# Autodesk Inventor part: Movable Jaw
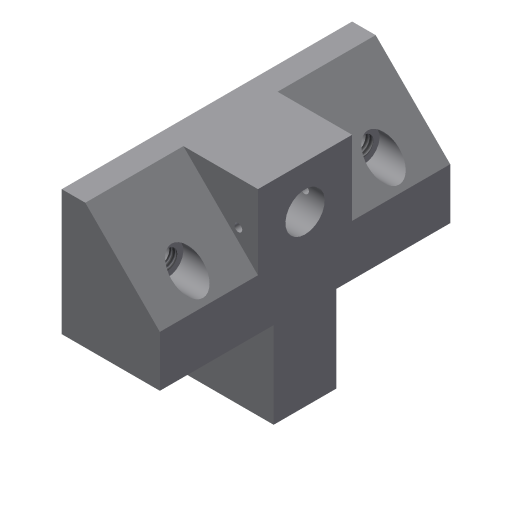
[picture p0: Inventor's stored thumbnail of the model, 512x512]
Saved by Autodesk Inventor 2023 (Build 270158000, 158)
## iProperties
Shininess: 77.0
Length Units: 11269
Angle Units: 11279
Time Units: 11290
Mass Units: 11283
Length Display Precision: 3
Angle Display Precision: 2
Created: 2002-02
Part Number: Movable Jaw
Document SubType Name: Modeling
Designer: ***
Density: 1 g/cm^3
Material: Generic
Mass: 56.5588 g
Surface Area: 124.299 cm^2
Volume: 56.5588 cm^3
Appearance: Default
Density: 0.0
Volumn: 0.0
Area: 0.0
PropertySet Name: Model Information
Control State: 0
Master: False
Checked Out: False
Author: ***
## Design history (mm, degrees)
sketch "Sketch2"
  geometry: L1 (2.39, 41.509)-(2.39, 9.509); L2 (2.39, 9.509)-(-22.61, 9.509); L3 (-22.61, 9.509)-(-22.61, 22.509); L4 (-22.61, 22.509)-(-3.61, 41.509); L5 (-3.61, 41.509)-(2.39, 41.509)
  constraints: 10 end point, 2 parallel, 1 perpendicular, 1 vertical
  dimensions: "d0" = 25 distance of L1.end L2.end; "d2" = 13 distance of L2.end L3.end; "d3" = 32 distance between parallel lines of L5 L2; "d4" = 6 distance of L4.end L1.start
extrude "Extrusion1" new body sketch "Sketch2" stored distance "d5" = 74; taper "d6" = 0 deg
sketch "Sketch3"
  geometry: L1 (-19, 25)-(11, 25); L2 (11, 25)-(11, 49); L3 (11, 49)-(-19, 49); L4 (-19, 49)-(-19, 25); L5 (0, 0)-(13, 0) reference; L6 (-19, 74)-(-19, 0) reference; L7 (11.924, 29)-(35, 29); L8 (35, 29)-(35, 45); L9 (35, 45)-(11.924, 45); L10 (11.924, 45)-(11.924, 29); L11 (13, 74)-(13, 0) reference
  constraints: 16 end point, 4 parallel, 2 horizontal, 2 perpendicular, 1 collinear
  dimensions: "d7" = 24 distance of L3.end L1.start; "d8" = 30 distance of L1.start L1.end; "d9" = 25 distance between parallel lines of L5 L1; "d10" = 16 distance of L7.end L8.end; "d11" = 4 distance between parallel lines of L3 L9; "d12" = 22 distance between parallel lines of L11 L8
extrude "Extrusion2" join sketch "Sketch3" distance "d13" = 25; taper "d14" = 0 deg
sketch "Sketch4"
  geometry: L1 (-19, -25)-(-19, -49) reference; L2 (-19, -49)-(0, -49) reference; 1 further point
  dimensions: "d15" = 11 distance from line of L1 point (-8, -37); "d16" = 12 distance from line of L2 point (-8, -37)
hole "Hole1" sketch "Sketch4" at (-8, -37) diameter "d17" = 10; stored, may be unused: countersink angle "d21" = 82 deg, drill point angle "d23" = 0 deg; dims "d18" = 6, "d19" = 4, "d20" = 2, "d22" = 13
sketch "Sketch5"
  geometry: L1 (-19, -49)-(-19, -74) reference; L2 (0, -74)-(13, -74) reference; 1 further point
  dimensions: "d24" = 14 distance from line of L1 point (-5, -62); "d25" = 12 distance from line of L2 point (-5, -62)
hole "Hole2" sketch "Sketch5" at (-5, -62) diameter "d26" = 4.917; stored, may be unused: countersink angle "d30" = 82 deg, drill point angle "d32" = 0 deg; dims "d27" = 12, "d28" = 8, "d29" = 10, "d31" = 17.1
mirror "Mirror1"
sketch "Sketch6"
  geometry: L1 (0, 19)-(0, 0) reference; 1 further point
  dimensions: "d33" = 5 distance from line of L1 point (-5, 8); "d34" = 11 vertical distance of L1.start point (-5, 8)
hole "Hole3" sketch "Sketch6" at (-5, 8) diameter "d35" = 2; stored, may be unused: countersink angle "d39" = 82 deg, drill point angle "d41" = 0 deg; dims "d36" = 6, "d37" = 8, "d38" = 10, "d40" = 13
body "Solid1"
